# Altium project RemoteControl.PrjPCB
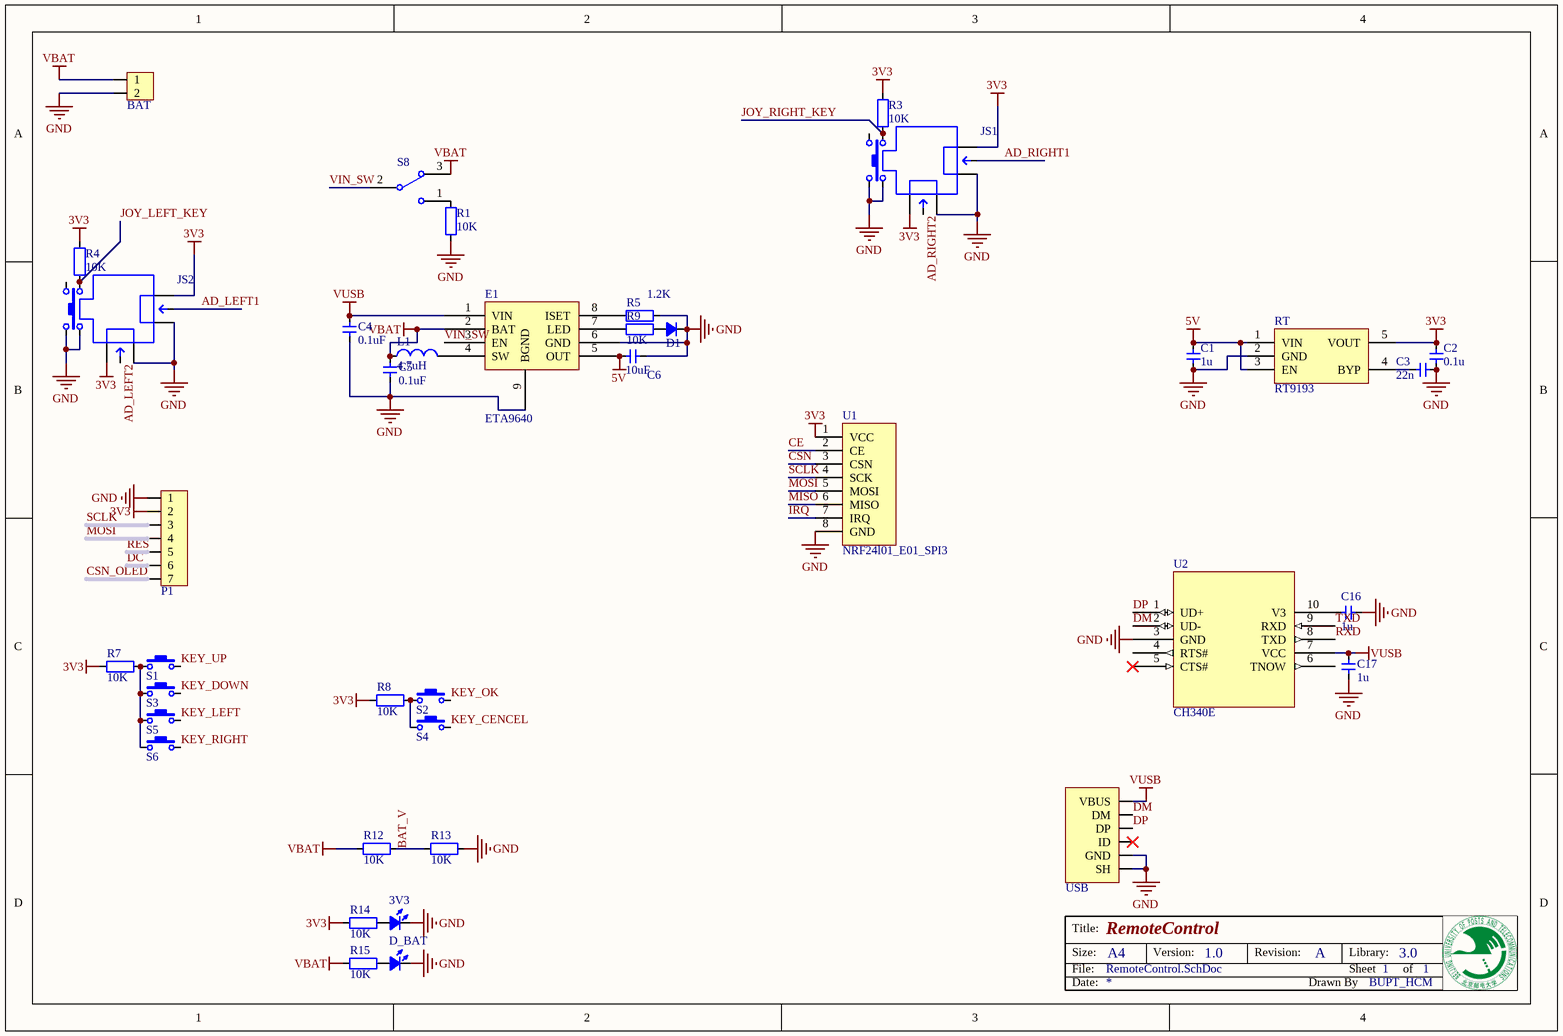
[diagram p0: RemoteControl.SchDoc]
2 sheets, 60 parts. Net scope: global (net labels, ports and power ports of the same name join across sheets).
Sheets:
  RemoteControl.SchDoc
  Core.SchDoc

## Sheet RemoteControl.SchDoc: RemoteControl
size A4; CompanyName: BUPT; DrawnBy: BUPT_HCM; Engineer: BUPT_HCM; Organization: BUPT_Robot; Revision: A; SheetNumber: 1; SheetTotal: 1; Version: 1.0; LibVersion: 3.0

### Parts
3V3  LED_0805  [LED_0805_RED]  (value not drawn)
BAT  HDR1x2_2.54  [HDR1X2_2.54_90]  (value not drawn)
C1  value 1u  [CAP_0603]  (hidden comment: Cap_0603)
C2  value 0.1u  [CAP_0603]  (hidden comment: Cap_0603)
C3  value 22n  [CAP_0603]  (hidden comment: Cap_0603)
C4  value 0.1uF  [CAP_0603]  (hidden comment: Cap_0603)
C5  value 0.1uF  [CAP_0603]  (hidden comment: Cap_0603)
C6  value 10uF  [CAP_0603]  (hidden comment: Cap_0603)
C16  value 1u  [CAP_0603]  (hidden comment: Cap_0603)
C17  value 1u  [CAP_0603]  (hidden comment: Cap_0603)
D1  D_0805  [LED_0805_YELLOW]  (value not drawn)
D_BAT  LED_0805  [LED_0805_RED]  (value not drawn)
E1  ETA9640  [SOP_E150_8 -with_PADs]
JS1  JoyStick  [JoyStick]  (value not drawn)
JS2  JoyStick  [JoyStick]  (value not drawn)
L1  value 4.7uH  [IND_CD32]  (hidden comment: Ind_CD32)
P1  HDR1x7_2.54  [HDR1X7_2.54_180]  (value not drawn)
R1  value 10K  [RES_0603]  (hidden comment: Res_0603)
R3  value 10K  [RES_0603]  (hidden comment: Res_0603)
R4  value 10K  [RES_0603]  (hidden comment: Res_0603)
R5  value 1.2K  [RES_0603]  (hidden comment: Res_0603)
R7  value 10K  [RES_0603]  (hidden comment: Res_0603)
R8  value 10K  [RES_0603]  (hidden comment: Res_0603)
R9  value 10K  [RES_0603]  (hidden comment: Res_0603)
R12  value 10K  [RES_0603]  (hidden comment: Res_0603)
R13  value 10K  [RES_0603]  (hidden comment: Res_0603)
R14  value 10K  [RES_0603]  (hidden comment: Res_0603)
R15  value 10K  [RES_0603]  (hidden comment: Res_0603)
RT  RT9193  [SOT23-5]
S1  ButtonTACT_3x6x2.5_180  [ButtonTACT_3x6x2.5_180]  (value not drawn)
S2  ButtonTACT_3x6x2.5_180  [ButtonTACT_3x6x2.5_180]  (value not drawn)
S3  ButtonTACT_3x6x2.5_180  [ButtonTACT_3x6x2.5_180]  (value not drawn)
S4  ButtonTACT_3x6x2.5_180  [ButtonTACT_3x6x2.5_180]  (value not drawn)
S5  ButtonTACT_3x6x2.5_180  [ButtonTACT_3x6x2.5_180]  (value not drawn)
S6  ButtonTACT_3x6x2.5_180  [ButtonTACT_3x6x2.5_180]  (value not drawn)
S8  SwitchSPDT_2.8x6.6_90  [SwitchSPDT_2.8X6.6_90]  (value not drawn)
U1  NRF24l01_E01_SPI3  [E01-ML01SP2]
U2  CH340E  [MSOP10]
USB  USB_Micro  [USB_Micro-AB]  (value not drawn)

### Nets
3V3: C2.2 JS1.1 JS1.6 JS2.1 JS2.6 P1.2 R3.2 R4.2 R7.2 R8.2 R14.1 RT.5(VOUT) U1.1(VCC)
5V: C1.2 C6.1 E1.5(OUT) RT.1(VIN) RT.3(EN)
GND: 3V3.2(K) BAT.2 C1.1 C2.1 C3.1 C4.2 C5.2 C6.2 C16.1 C17.2 D1.2(K) D_BAT.2(K) E1.6(GND) E1.9(BGND) JS1.3 JS1.4 JS1.8 JS1.10 JS2.3 JS2.4 JS2.8 JS2.10 P1.1 R1.1 R5.1 R13.1 RT.2(GND) U1.8(GND) U2.3(GND) USB.0(SH) USB.5(GND)
VBAT: BAT.1 C5.1 E1.2(BAT) L1.1 R12.2 R15.1 S8.3
VUSB: C4.1 C17.1 E1.1(VIN) U2.7(VCC) USB.1(VBUS)
AD_LEFT1: JS2.5
AD_LEFT2: JS2.2
AD_RIGHT1: JS1.5
AD_RIGHT2: JS1.2
BAT_V: R12.1 R13.2
CE: U1.2(CE)
CSN: U1.3(CSN)
CSN_OLED: P1.7
DC: P1.6
DM: U2.2(UD-) USB.2(DM)
DP: U2.1(UD+) USB.3(DP)
IRQ: U1.7(IRQ)
JOY_LEFT_KEY: JS2.9 R4.1
JOY_RIGHT_KEY: JS1.9 R3.1
KEY_CENCEL: S4.2
KEY_DOWN: S3.2
KEY_LEFT: S5.2
KEY_OK: S2.2
KEY_RIGHT: S6.2
KEY_UP: S1.2
MISO: U1.6(MISO)
MOSI: P1.4 U1.5(MOSI)
RES: P1.5
RXD: U2.8(TXD)
SCLK: P1.3 U1.4(SCK)
TXD: U2.9(RXD)
VIN_SW: E1.3(EN) S8.2
Net3V3_1: 3V3.1(A) R14.2
NetC3_2: C3.2 RT.4(BYP)
NetC16_2: C16.2 U2.10(V3)
NetD1_1: D1.1(A) R9.1
NetD_BAT_1: D_BAT.1(A) R15.2
NetE1_4: E1.4(SW) L1.2
NetE1_7: E1.7(LED) R9.2
NetE1_8: E1.8(ISET) R5.2
NetR1_2: R1.2 S8.1
NetR7_1: R7.1 S1.1 S3.1 S5.1 S6.1
NetR8_1: R8.1 S2.1 S4.1

Not connected (* = marked no-connect by the designer): JS1 7; JS2 7; U2 4(RTS#) 5(CTS#)* 6(TNOW); USB 4(ID)*

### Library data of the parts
3V3 D_BAT = LED_0805: LED
BAT = HDR1x2_2.54: Header
C1-C6 C16 C17 = Cap_0603: Capacitor
L1 = Ind_CD32: Inductor
P1 = HDR1x7_2.54T: Header
R1 R3-R5 R7-R9 R12-R15 = Res_0603: Resistor
RT = RT9193: Power
S1-S6 = ButtonTACT_3x6x2.5_180: Button
S8 = SwitchSPDT_2.8x6.6_90: Switch
U1 = NRF24l01_E01_SPI2
U2 = CH340E: USB to TTL Serial / UART
USB = USB_Micro: USB

## Sheet Core.SchDoc
size A4
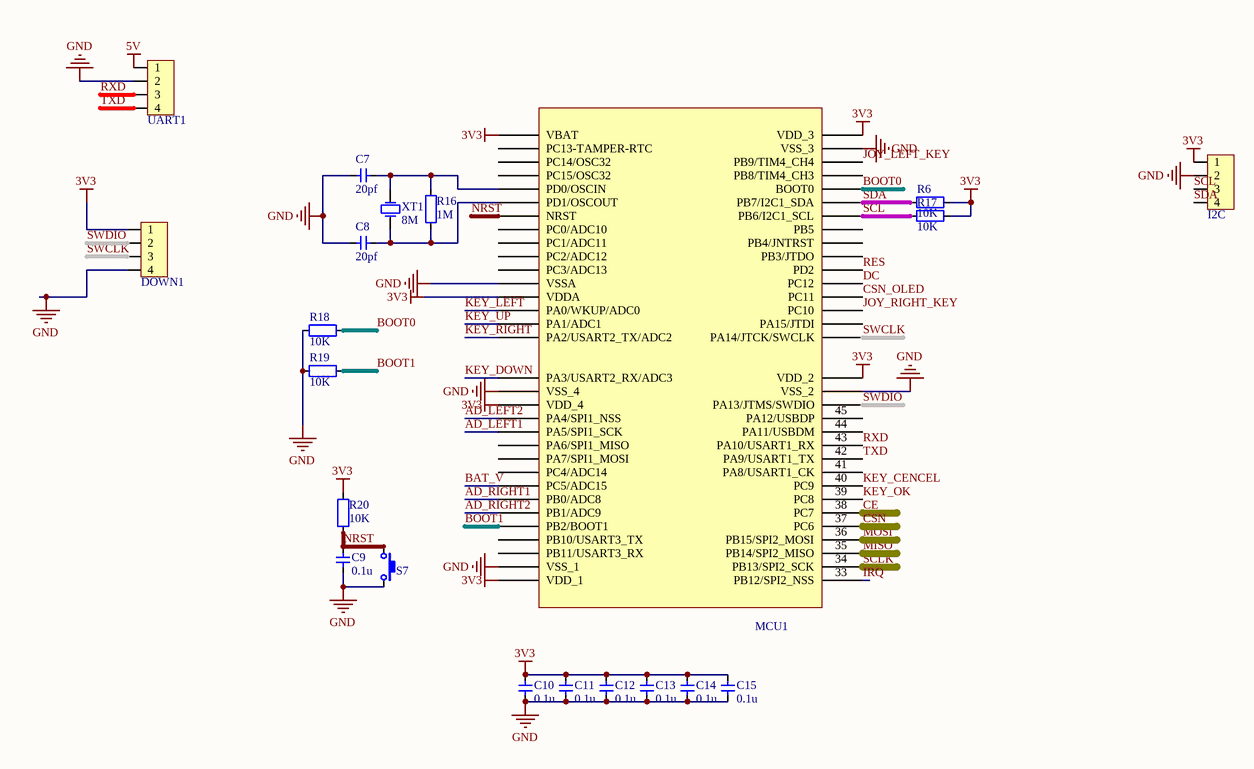
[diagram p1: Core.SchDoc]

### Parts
C7  value 20pf  [CAP_0603]  (hidden comment: Cap_0603)
C8  value 20pf  [CAP_0603]  (hidden comment: Cap_0603)
C9  value 0.1u  [CAP_0603]  (hidden comment: Cap_0603)
C10  value 0.1u  [CAP_0603]  (hidden comment: Cap_0603)
C11  value 0.1u  [CAP_0603]  (hidden comment: Cap_0603)
C12  value 0.1u  [CAP_0603]  (hidden comment: Cap_0603)
C13  value 0.1u  [CAP_0603]  (hidden comment: Cap_0603)
C14  value 0.1u  [CAP_0603]  (hidden comment: Cap_0603)
C15  value 0.1u  [CAP_0603]  (hidden comment: Cap_0603)
DOWN1  HDR1x4_2.54  [HDR1x4_2.54_180]  (value not drawn)
I2C  HDR1x4_2.54  [HDR1x4_2.54_180]  (value not drawn)
MCU1  STM32F103RC  [LQFP_P0.5_64]  (value not drawn)
R6  value 10K  [RES_0603]  (hidden comment: Res_0603)
R16  value 1M  [RES_0603]  (hidden comment: Res_0603)
R17  value 10K  [RES_0603]  (hidden comment: Res_0603)
R18  value 10K  [RES_0603]  (hidden comment: Res_0603)
R19  value 10K  [RES_0603]  (hidden comment: Res_0603)
R20  value 10K  [RES_0603]  (hidden comment: Res_0603)
S7  ButtonTACT_3x4x2_180  [ButtonTACT_3x4x2_180H]  (value not drawn)
UART1  HDR1x4_2.54  [HDR1x4_2.54_180]  (value not drawn)
XT1  value 8M  [XT_5032_2]  (hidden comment: XTAL_5032_2P)

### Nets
3V3: C10.2 C11.2 C12.2 C13.2 C14.2 C15.2 DOWN1.1 I2C.1 MCU1.1(VBAT) MCU1.13(VDDA) MCU1.19(VDD_4) MCU1.32(VDD_1) MCU1.48(VDD_2) MCU1.64(VDD_3) R6.2 R17.2 R20.1
5V: UART1.1
GND: C7.1 C8.1 C9.1 C10.1 C11.1 C12.1 C13.1 C14.1 C15.1 DOWN1.4 I2C.2 MCU1.12(VSSA) MCU1.18(VSS_4) MCU1.31(VSS_1) MCU1.47(VSS_2) MCU1.63(VSS_3) R18.2 R19.2 S7.2 UART1.2
AD_LEFT1: MCU1.21(PA5/SPI1_SCK)
AD_LEFT2: MCU1.20(PA4/SPI1_NSS)
AD_RIGHT1: MCU1.26(PB0/ADC8)
AD_RIGHT2: MCU1.27(PB1/ADC9)
BAT_V: MCU1.25(PC5/ADC15)
BOOT0: MCU1.60(BOOT0) R18.1
BOOT1: MCU1.28(PB2/BOOT1) R19.1
CE: MCU1.38(PC7)
CSN: MCU1.37(PC6)
CSN_OLED: MCU1.52(PC11)
DC: MCU1.53(PC12)
IRQ: MCU1.33(PB12/SPI2_NSS)
JOY_LEFT_KEY: MCU1.62(PB9/TIM4_CH4)
JOY_RIGHT_KEY: MCU1.51(PC10)
KEY_CENCEL: MCU1.40(PC9)
KEY_DOWN: MCU1.17(PA3/USART2_RX/ADC3)
KEY_LEFT: MCU1.14(PA0/WKUP/ADC0)
KEY_OK: MCU1.39(PC8)
KEY_RIGHT: MCU1.16(PA2/USART2_TX/ADC2)
KEY_UP: MCU1.15(PA1/ADC1)
MISO: MCU1.35(PB14/SPI2_MISO)
MOSI: MCU1.36(PB15/SPI2_MOSI)
NRST: C9.2 MCU1.7(NRST) R20.2 S7.1
RES: MCU1.54(PD2)
RXD: MCU1.43(PA10/USART1_RX) UART1.3
SCL: I2C.3 MCU1.58(PB6/I2C1_SCL) R17.1
SCLK: MCU1.34(PB13/SPI2_SCK)
SDA: I2C.4 MCU1.59(PB7/I2C1_SDA) R6.1
SWCLK: DOWN1.3 MCU1.49(PA14/JTCK/SWCLK)
SWDIO: DOWN1.2 MCU1.46(PA13/JTMS/SWDIO)
TXD: MCU1.42(PA9/USART1_TX) UART1.4
NetC7_2: C7.2 MCU1.5(PD0/OSCIN) R16.2 XT1.2(OSC2)
NetC8_2: C8.2 MCU1.6(PD1/OSCOUT) R16.1 XT1.1(OSC1)

Not connected (* = marked no-connect by the designer): MCU1 2(PC13-TAMPER-RTC) 3(PC14/OSC32) 4(PC15/OSC32) 8(PC0/ADC10) 9(PC1/ADC11) 10(PC2/ADC12) 11(PC3/ADC13) 22(PA6/SPI1_MISO) 23(PA7/SPI1_MOSI) 24(PC4/ADC14) 29(PB10/USART3_TX) 30(PB11/USART3_RX) 41(PA8/USART1_CK) 44(PA11/USBDM) 45(PA12/USBDP) 50(PA15/JTDI) 55(PB3/JTDO) 56(PB4/JNTRST) 57(PB5) 61(PB8/TIM4_CH3)

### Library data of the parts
C7-C15 = Cap_0603: Capacitor
DOWN1 I2C UART1 = HDR1x4_2.54: Header
MCU1 = STM32F103RC: MCU
R6 R16-R20 = Res_0603: Resistor
S7 = ButtonTACT_3x4x2_180: Button
XT1 = XTAL_5032_2P: Crystal Oscillator

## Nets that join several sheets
3V3: RemoteControl (13 pins), Core (17 pins)
5V: RemoteControl (5 pins), Core (UART1.1)
GND: RemoteControl (31 pins), Core (20 pins)
AD_LEFT1: RemoteControl (JS2.5), Core (MCU1.21)
AD_LEFT2: RemoteControl (JS2.2), Core (MCU1.20)
AD_RIGHT1: RemoteControl (JS1.5), Core (MCU1.26)
AD_RIGHT2: RemoteControl (JS1.2), Core (MCU1.27)
BAT_V: RemoteControl (R12.1 R13.2), Core (MCU1.25)
CE: RemoteControl (U1.2), Core (MCU1.38)
CSN: RemoteControl (U1.3), Core (MCU1.37)
CSN_OLED: RemoteControl (P1.7), Core (MCU1.52)
DC: RemoteControl (P1.6), Core (MCU1.53)
IRQ: RemoteControl (U1.7), Core (MCU1.33)
JOY_LEFT_KEY: RemoteControl (JS2.9 R4.1), Core (MCU1.62)
JOY_RIGHT_KEY: RemoteControl (JS1.9 R3.1), Core (MCU1.51)
KEY_CENCEL: RemoteControl (S4.2), Core (MCU1.40)
KEY_DOWN: RemoteControl (S3.2), Core (MCU1.17)
KEY_LEFT: RemoteControl (S5.2), Core (MCU1.14)
KEY_OK: RemoteControl (S2.2), Core (MCU1.39)
KEY_RIGHT: RemoteControl (S6.2), Core (MCU1.16)
KEY_UP: RemoteControl (S1.2), Core (MCU1.15)
MISO: RemoteControl (U1.6), Core (MCU1.35)
MOSI: RemoteControl (P1.4 U1.5), Core (MCU1.36)
RES: RemoteControl (P1.5), Core (MCU1.54)
RXD: RemoteControl (U2.8), Core (MCU1.43 UART1.3)
SCLK: RemoteControl (P1.3 U1.4), Core (MCU1.34)
TXD: RemoteControl (U2.9), Core (MCU1.42 UART1.4)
